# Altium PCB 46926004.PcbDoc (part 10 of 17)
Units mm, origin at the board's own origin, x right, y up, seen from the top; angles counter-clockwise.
Board outline 250 x 200 mm, 6 copper layers (Top Layer, INT1_GND, INT2_SIG, INT3_SIG, INT4_GND, Bottom Layer), stack 1.71 mm thick; 1450 components, 1293 nets, 5656 pads, 2307 vias.
Unrouted connection lines stored in the file: 2.
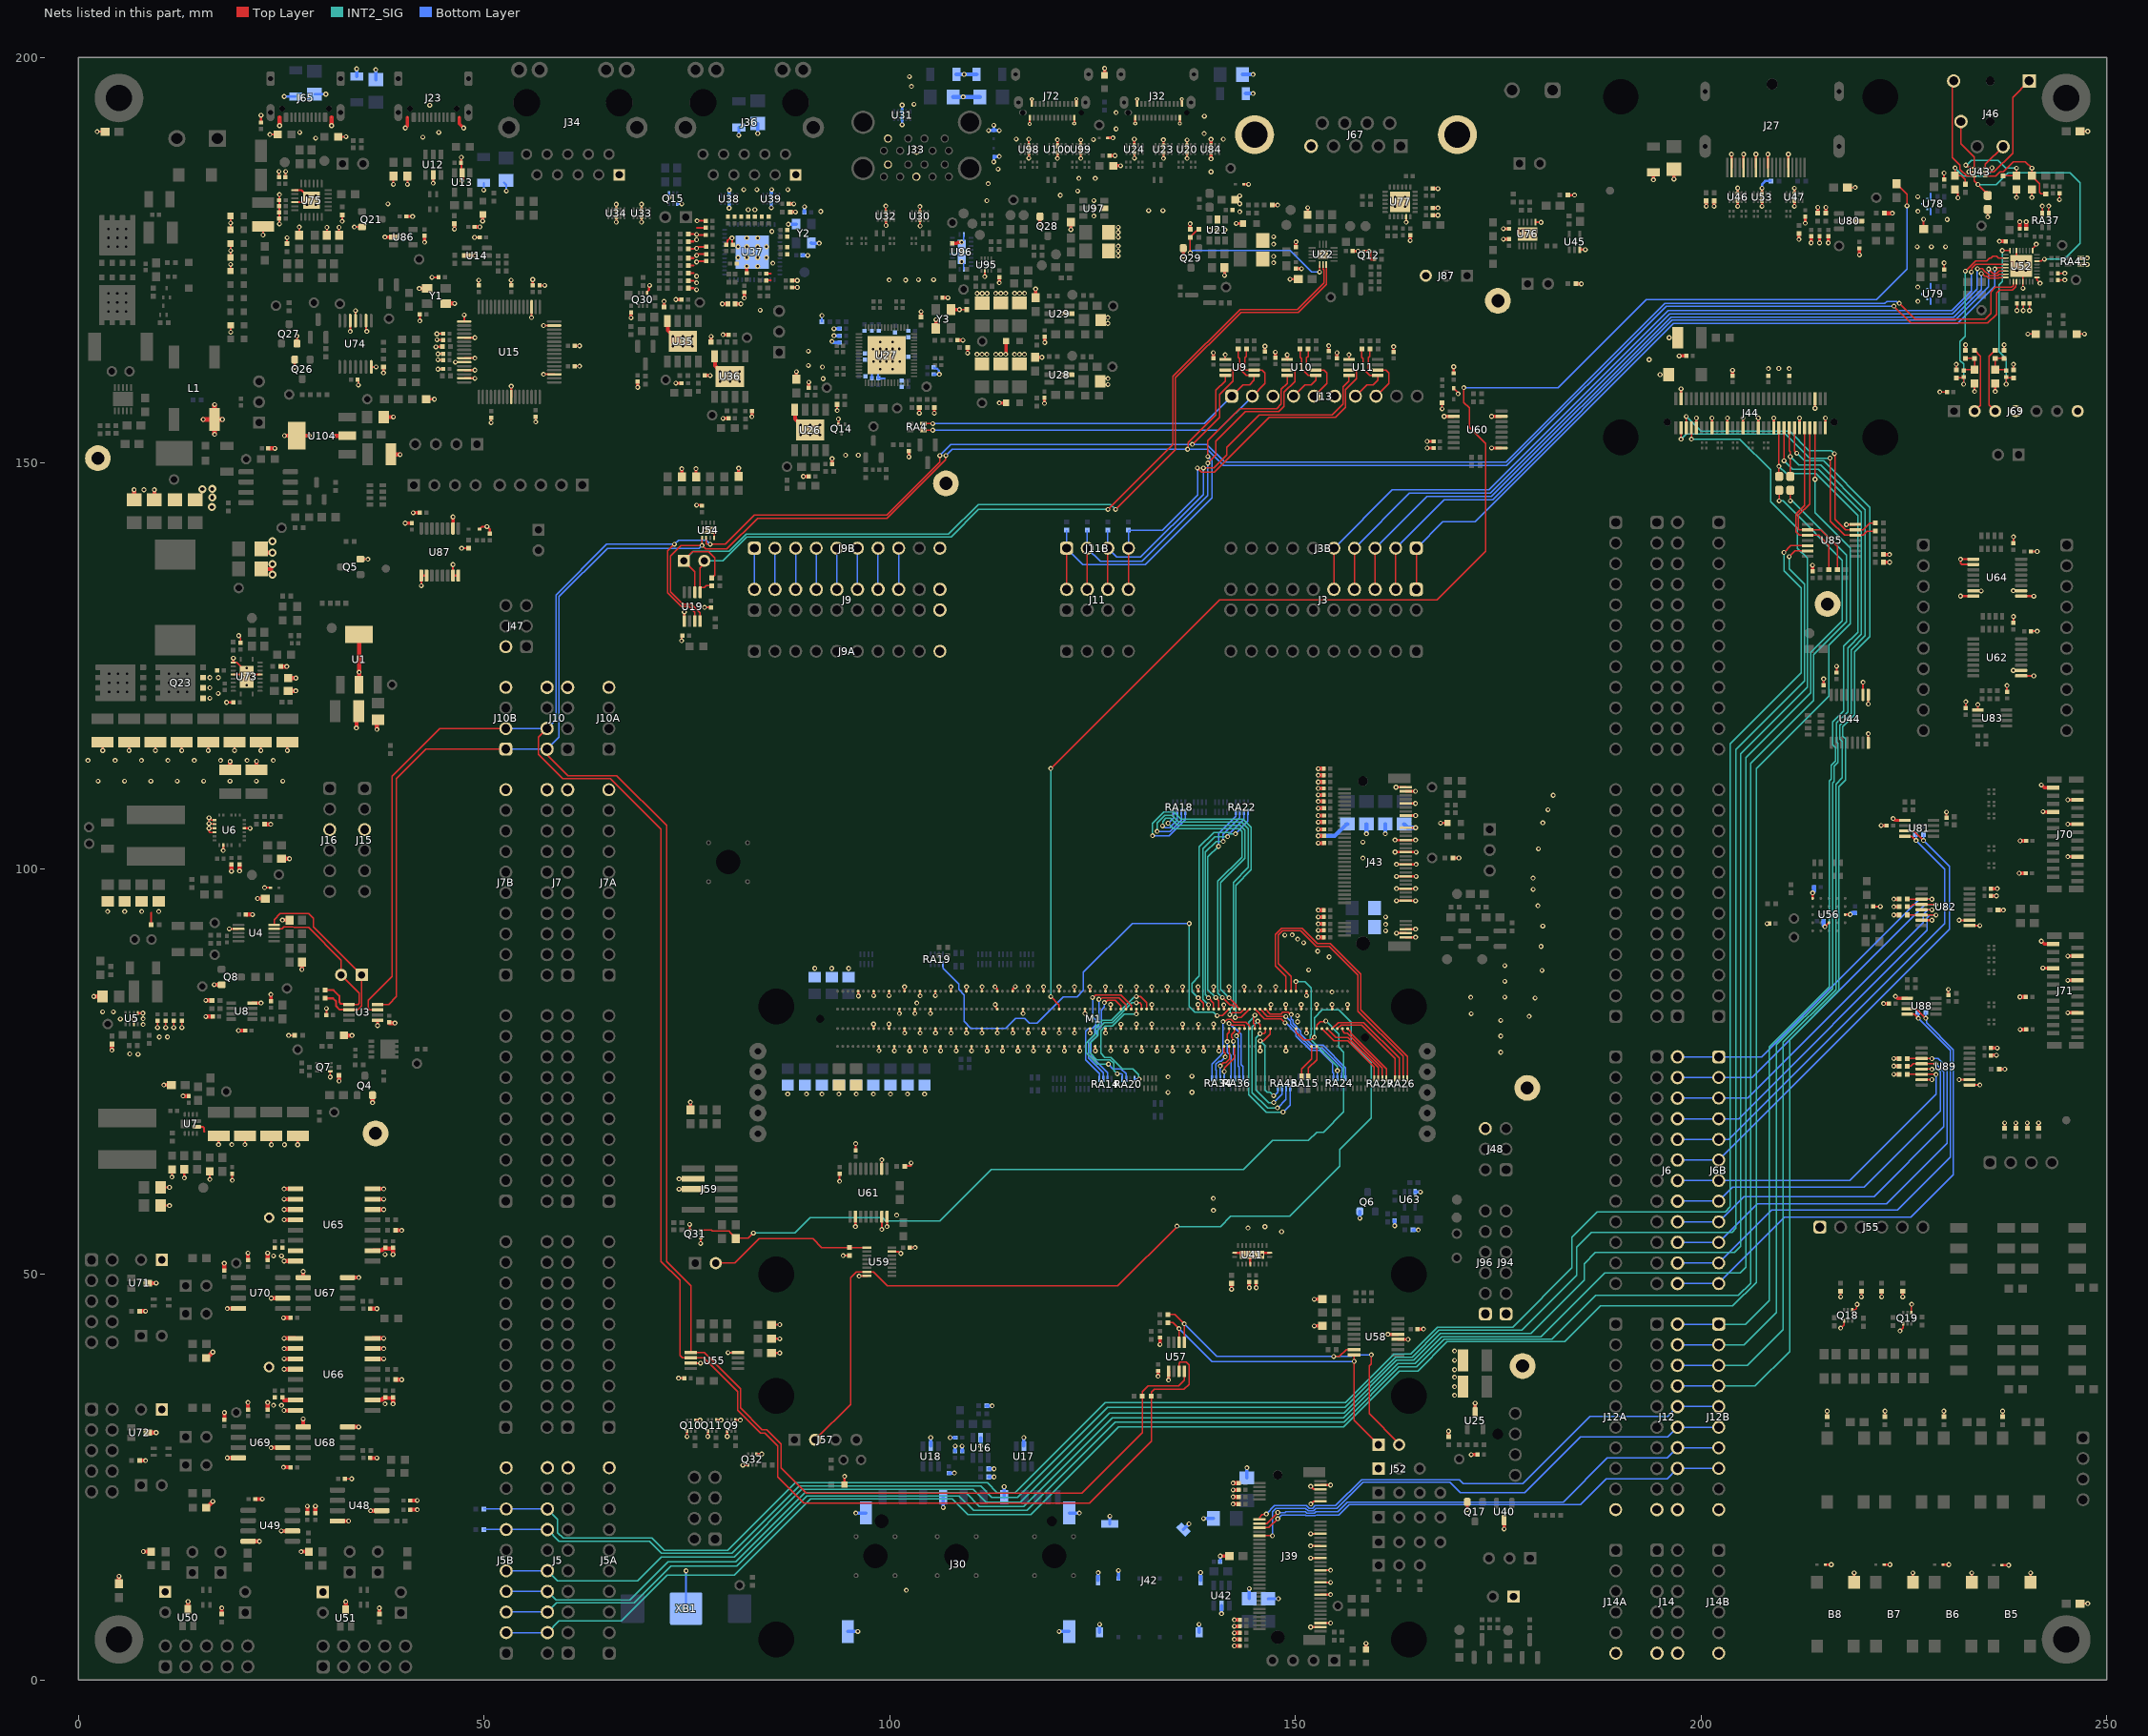
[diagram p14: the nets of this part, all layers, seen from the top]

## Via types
v1: diameter 0.6, hole 0.3, Top Layer to Bottom Layer, tented both sides, 2171 vias
v2: diameter 0.6, hole 0.3, Top Layer to Bottom Layer, 48 vias
v3: diameter 1, hole 0.5, Top Layer to Bottom Layer, tented both sides, 37 vias
v4: diameter 0.5, hole 0.2, Top Layer to Bottom Layer, tented both sides, 34 vias
v5: diameter 0.6, hole 0.3, Top Layer to Bottom Layer, tented bottom, 17 vias

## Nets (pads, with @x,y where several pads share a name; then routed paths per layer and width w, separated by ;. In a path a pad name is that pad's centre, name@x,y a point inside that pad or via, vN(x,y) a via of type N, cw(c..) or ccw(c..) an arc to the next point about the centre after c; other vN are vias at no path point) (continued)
GND: (continued)
  other v1: 102.035,11.07 79.202,32.039 81.582,32.039 37.79,34.035 169.6,35.1 169.6,36.15 169.6,37.325 169.6,38.25 169.6,39.4 169.6,40.55 37.795,52.45 148.3,55.26 144.151,55.72 146.233,55.875 100.85,57.3 139.895,57.891 139.879,59.358 18.905,66 25.405,65.983 87.425,72.235 89.725,72.235 91.639,72.235 93.739,72.235 95.865,72.235 97.989,72.235 100.089,72.235 102.189,72.235 104.289,72.235 134.3,72.425 137.25,72.45 231.804,73.998 134.3,74.342 137.25,74.425 7.35,77.125 6.325,77.175 175.3,77.375 9.972,79.254 10.972,79.254 175.3,79.375 7.972,80.801 150.262,81.134 175.3,81.3 5.175,81.475 7.975,81.5 178.8,81.8 150.26,81.882 171.658,82.122 2.975,82.35 4.3,82.35 22.5,83.45 103.334,83.439 179.528,84.057 171.608,84.147 175.8,84.175 230.473,85.118 107.537,85.444 175.8,86.125 180.4,87.463 151.629,87.526 90.75,87.715 92.85,87.715 94.925,87.715 175.8,88.05 154.152,89.126 152.741,89.839 180.281,90.424 151.024,90.883 150.271,91.329 148.7,91.815 149.609,91.843 161.115,92.35 180.49,92.931 161.12,93.135 231.805,93.65 161.115,94.049 218.375,94.36 3.6,94.731 5.7,94.731 7.8,94.731 9.9,94.731 179.891,95.427 179.301,97.45 179.291,98.835 19.862,99.714 158.312,101.3 179.95,102.452 158.312,103.275 180.49,105.66 230.235,106.97 181.125,107.262 181.771,109.05 2.433,110.8 5.683,110.8 8.933,110.8 12.183,110.8 15.433,110.8 18.683,110.8 21.933,110.8 25.183,110.8 1.175,113.35 4.525,113.35 7.775,113.35 11.025,113.35 14.275,113.35 17.525,113.35 20.775,113.35 24.025,113.35 17.243,121.602 16.192,122.295 219.961,122.989 16.192,123.565 17.245,123.565 241.014,123.764 34.6,124.232 238.486,124.436 241.014,133.589 231.986,133.611 234.514,134.239 238.486,134.261 213.728,137.407 223.231,138.728 77.12,141.713 78.12,141.713 8.08,146.71 94.549,150.97 96.12,150.97 126.886,159.682 91.791,160.399 126.886,160.407 194.95,160.9 203.878,161.445 208.3,161.654 210.85,161.654 209.575,161.66 91.695,161.835 89.976,162.034 193.6,162.75 110.749,163.409 111.372,163.409 111.975,163.409 113.073,163.409 113.696,163.409 115.373,163.409 115.996,163.409 116.599,163.409 89.976,163.791 196.065,165.45 126.88,167.213 126.88,167.938 84.035,168.835 79.367,169.627 226.725,169.925 82.061,170.348 110.776,170.918 111.399,170.918 112.002,170.918 113.064,170.928 113.687,170.928 114.289,170.928 115.388,170.928 116.012,170.928 116.614,170.928 76.195,171.367 226.7,171.7 76.195,172.217 99.925,172.572 101.96,172.56 103.533,172.6 105.412,172.597 76.195,173.037 85.589,174.641 147.31,174.686 76.195,174.788 108.86,174.825 147.315,175.471 128.15,175.532 76.195,175.603 128.15,176.135 76.195,176.469 226.625,176.65 228.375,176.65 230.125,176.65 128.15,176.758 147.31,176.986 76.195,177.522 128.15,177.836 147.31,177.886 76.195,178.19 128.15,178.438 85.475,178.55 139.42,178.739 140.37,178.736 141.32,178.739 128.15,179.062 99.542,179.288 163.649,179.688 230.325,180.025 125.161,180.448 143.151,180.976 91.5,181.025 226.725,181.041 131.9,181.113 133.663,181.113 82.55,181.225 83.375,181.225 125.158,181.398 103.712,181.629 200.62,181.648 201.595,181.648 38.15,181.95 143.136,181.963 111.971,182.343 125.161,182.348 226.7,182.816 143.12,182.95 121.011,183.021 123.175,183.529 82,183.7 83.625,183.7 87.45,183.7 112.133,184.45 123.31,185.093 125.328,185.093 139.6,185.901 113.35,186.225 136.637,187.567 136.65,189.825 125.111,189.87 141.115,189.921 115.581,189.94 29.241,190.05 42.45,190.164 138.746,190.624 27.27,190.76 44.425,190.76 127.892,191.189 138.783,192.76 127.9,193.2 43.305,194.101 102.986,194.228 102.675,196.425 102.425,197.625
  other v2: 88.991,153.481 90.191,153.481 91.391,153.481 90.191,154.681 91.391,154.681 79.095,160.067 80.295,160.067 81.495,160.067 80.295,161.267 81.495,161.267 73.29,164.404 74.49,164.404 75.69,164.404 74.49,165.604 75.69,165.604 238.921,173.725 240.021,173.725 83.728,174.25 240.021,174.825 81.3,175.321 82.371,175.321 83.728,175.321 84.8,175.321 81.3,176.678 82.371,176.678 83.728,176.678 84.8,176.678 82.371,177.75 83.728,177.75 177.813,177.838 178.6,177.838 179.387,177.838 177.813,178.625 178.6,178.625 179.387,178.625 162.3,181.6 163.5,181.6 29.275,181.85 162.3,182.8 163.5,182.8 29.275,182.95
  other v3: 23.925,136.24 23.925,137.535 23.925,140.355 16.455,144.575 16.485,145.755 15.29,146.795 16.485,146.805
  other v5: 100.368,161.58 100.378,162.495 97.983,162.52 98.808,162.51 99.604,162.5 101.228,162.515 98.823,163.29 100.368,163.3 97.968,164.065 98.803,164.07 99.594,164.05 100.363,164.07 101.168,164.07 100.373,164.92 98.818,164.935 153.396,175.715
GND_ISO1: C254.1 C255.1 C257.1 C261.1 C262.1 C263.2 C356.1 J89.1 R381.2 U65.9 U65.10 U65.11 U65.12 U65.15 U65.16 U67.5 U70.2 U70.8 U71.3 X85.1 | length 16.4
  Top Layer w0.15: C263.2@15.775,39.667 C263.2@15.825,39.667 ; v1@16.576,40.418 v1(16.576,40.429) ; U65.16@26.743,51.642 U65.16@26.748,51.647
  Top Layer w0.5: R381.2@7.55,45.467 v1(8.275,45.467) ; U71.3@8.575,48.917 v1(9.575,48.917) ; C263.2@15.825,39.667 v1@16.576,40.418 ; C261.1@17.978,50.585 v1(17.978,51.358) ; v1(18.351,45.794) U70.8@19.718,45.794 ; C255.1@20.9,51.85 v1(20.9,52.623) ; C262.1@23.323,51.85 v1(23.323,52.623) ; v1(23.765,47.065) U70.2@25.181,47.065 ; v1(25.282,44.64) C356.1@26.055,44.64 ; v1(25.353,56.725) U65.12@26.746,56.725 ; v1(25.353,57.995) U65.11@26.746,57.995 ; v1(25.353,59.265) U65.10@26.746,59.265 ; v1(25.353,60.535) U65.9@26.746,60.535 ; v1(25.355,51.647) U65.16@26.748,51.647 ; U67.5@27.705,49.606 v1(27.705,50.355)
  other v1: 24.045,52.275 25.03,52.275
GND_ISO2: C253.1 C256.1 C258.1 C259.1 C260.1 C264.2 C357.1 J85.1 R380.2 U66.9 U66.10 U66.11 U66.12 U66.15 U66.16 U68.5 U69.2 U69.8 U72.3 X84.1 | length 17.8
  Top Layer w0.15: C264.2@15.775,21.25 C264.2@15.825,21.25 ; v1@16.576,22.001 v1(16.576,22.012) ; U69.8@19.717,27.375 U69.8@19.72,27.378 ; U66.16@26.743,33.225 U66.16@26.748,33.23
  Top Layer w0.5: R380.2@7.55,27.05 v1(8.275,27.05) ; U72.3@8.575,30.5 v1(9.575,30.5) ; C264.2@15.825,21.25 v1@16.576,22.001 ; C260.1@18,32.19 v1(18,32.963) ; v1(18.35,27.375) U69.8@19.717,27.375 ; C253.1@20.9,33.435 v1(20.9,34.208) ; C259.1@23.325,33.435 v1(23.325,34.208) ; v1(23.76,28.635) 23.767,28.641 24.9,28.641 U69.2@24.908,28.65 ; v1(25.275,26.223) C357.1@26.048,26.223 ; v1(25.35,33.225) U66.16@26.743,33.225 ; 25.352,34.498 U66.15@26.745,34.498 ; v1(25.352,38.308) U66.12@26.745,38.308 ; v1(25.352,39.578) U66.11@26.745,39.578 ; v1(25.352,40.848) U66.10@26.745,40.848 ; v1(25.352,42.118) U66.9@26.745,42.118 ; U68.5@27.705,31.188 v1(27.705,32.188)
  other v1: 24.04,33.853 25.025,33.853
GPIO_01: M1.D23 RA34.4 | length 4.5
  Top Layer w0.15: v1(141.225,75.002) 141.225,75.46 142.462,76.697 M1.D23@142.462,78.1
  Bottom Layer w0.15: RA34.4@141.225,74.15 v1(141.225,75.002)
GPIO_01_JMP: J9.2 J9B.1 | length 5.1
  Bottom Layer w0.15: J9.2@83.32,134.43 J9B.1@83.32,139.51
GPIO_02: M1.D24 RA34.3 | length 4.7
  Top Layer w0.15: v1(140.736,75.689) 141.155,76.108 141.449,76.108 141.896,76.555 141.896,77.262 141.827,77.331 M1.D24@141.827,78.1
  Bottom Layer w0.15: RA34.3@140.725,74.15 140.725,74.778 140.7,74.803 140.7,75.653 v1(140.736,75.689)
GPIO_02_JMP: J9.4 J9B.2 | length 5.1
  Bottom Layer w0.15: J9.4@85.86,134.43 J9B.2@85.86,139.51
GPIO_03: M1.D25 RA34.2 | length 4.6
  Top Layer w0.15: M1.D25@141.192,78.1 141.192,77.4 141.35,77.242 v1(141.35,76.799)
  Bottom Layer w0.15: RA34.2@140.225,74.15 140.225,75.171 140.211,75.185 140.211,75.906 140.579,76.274 140.825,76.274 v1(141.35,76.799)
GPIO_03_JMP: J9.6 J9B.3 | length 5.1
  Bottom Layer w0.15: J9.6@88.4,134.43 J9B.3@88.4,139.51
GPIO_04: M1.C20 RA34.1 | length 11.6
  Top Layer w0.15: v1(141.095,81.158) 141.181,81.244 141.395,81.244 141.604,81.453 142.047,81.453 142.438,81.062 143.905,81.062 144.367,80.601 M1.C20@144.367,80.3
  Bottom Layer w0.15: RA34.1@139.725,74.15 139.725,75.924 140.6,76.799 141.095,77.294 141.095,78.407 141.079,78.423 141.079,79.537 141.095,79.553 v1(141.095,81.158)
GPIO_04_JMP: J9.8 J9B.4 | length 5.1
  Bottom Layer w0.15: J9.8@90.94,134.43 J9B.4@90.94,139.51
GPIO_05: M1.C21 RA36.4 | length 10
  Top Layer w0.15: v1(141.821,80.928) 141.939,80.928 142.134,80.733 143.644,80.733 143.732,80.645 M1.C21@143.732,80.3
  Bottom Layer w0.15: v1(141.821,80.928) 142.337,80.412 142.484,80.412 143.3,79.596 143.3,75.879 143.55,75.629 RA36.4@143.55,74.15
GPIO_05_JMP: J9.10 J9B.5 | length 5.1
  Bottom Layer w0.15: J9.10@93.48,134.43 J9B.5@93.48,139.51
GPIO_06: M1.C22 RA36.3 | length 6.4
  Top Layer w0.15: v1(142.726,79.399) 142.726,79.506 143.097,79.876 M1.C22@143.097,80.3
  Bottom Layer w0.15: v1(142.726,79.399) 142.726,79.277 142.957,79.046 142.957,75.648 143.05,75.554 RA36.3@143.05,74.15
GPIO_06_JMP: J9.12 J9B.6 | length 5.1
  Bottom Layer w0.15: J9.12@96.02,134.43 J9B.6@96.02,139.51
GPIO_07: M1.C23 RA36.2 | length 6.4
  Top Layer w0.15: v1(142.353,78.718) 142.267,78.805 142.267,79.145 142.145,79.266 142.145,79.566 142.462,79.883 M1.C23@142.462,80.3
  Bottom Layer w0.15: v1(142.353,78.718) 142.353,77.141 142.55,76.944 RA36.2@142.55,74.15
GPIO_07_JMP: J9.14 J9B.7 | length 5.1
  Bottom Layer w0.15: J9.14@98.56,134.43 J9B.7@98.56,139.51
GPIO_08: M1.C24 RA36.1 | length 6.4
  Top Layer w0.15: v1(141.604,78.687) 141.604,79.6 141.826,79.822 M1.C24@141.827,80.3 M1.C24@141.827,80.3
  Bottom Layer w0.15: v1(141.604,78.687) 141.604,77.404 142.05,76.958 RA36.1@142.05,74.15
GPIO_08_JMP: J9.16 J9B.8 | length 5.1
  Bottom Layer w0.15: J9.16@101.1,134.43 J9B.8@101.1,139.51
GPIO_09_CSI_1: M1.B17 RA24.4 | length 15.1
  Top Layer w0.15: M1.B17@146.272,82.7 146.864,82.108 148.212,82.108 148.389,82.285 149.127,82.285 149.374,82.039 v1(149.496,82.039)
  Bottom Layer w0.15: v1(149.496,82.039) 149.496,81.508 149.689,81.315 149.689,80.965 150.671,79.983 150.671,79.64 152.069,78.242 153.401,78.242 156.175,75.469 RA24.4@156.175,74.178
GPIO_09_CSI_1_JMP: J6.2 J6B.1 R360.2 U82.3 | length 42.4
  Top Layer w0.15: R360.2@225.43,96.25 U82.3@227.18,96.25 v1@228.432,96.25
  Bottom Layer w0.15: J6.2@197.09,76.8 200.84,76.8 J6B.1@202.17,76.8 207.482,76.8 226.921,96.239 v1(228.443,96.239)
GPIO_10_CSI_1: M1.B18 RA24.3 | length 14.8
  Top Layer w0.15: M1.B18@145.637,82.7 146.529,81.808 148.752,81.808 v1(148.8,81.76)
  Bottom Layer w0.15: v1(148.8,81.76) 149.389,81.171 149.389,80.841 149.623,80.607 150.371,79.859 150.371,79.516 151.985,77.902 153.317,77.902 155.771,75.449 155.771,74.948 155.675,74.852 RA24.3@155.675,74.178
GPIO_10_CSI_1_JMP: J6.4 J6B.2 R361.2 U82.4 | length 44.3
  Top Layer w0.15: R361.2@225.43,95.319 225.453,95.343 225.867,95.343 226.124,95.6 U82.4@227.18,95.6 ; U82.4@227.187,95.592 v1@228.947,95.592
  Bottom Layer w0.15: J6.4@197.09,74.26 200.84,74.26 J6B.2@202.17,74.26 206.26,74.26 227.585,95.585 v1(228.955,95.585)
GPIO_11_CSI_1: M1.A11 RA24.2 | length 16
  Top Layer w0.18: v1(150.059,86.09) 150.083,86.066 M1.A11@150.083,84.9
  INT2_SIG w0.15: v1(150.059,86.09) 151.178,86.09 151.928,85.34 151.928,79.571 151.8,79.443 151.8,79.101 151.801,79.1 151.801,79.007 155.175,75.633 v1(155.175,75.095)
  Bottom Layer w0.15: RA24.2@155.175,74.178 v1(155.175,75.095)
GPIO_11_CSI_1_JMP: J6.6 J6B.3 U82.5 | length 42.8
  Top Layer w0.15: U82.5@227.18,94.95 v1@228.432,94.95
  Bottom Layer w0.15: J6.6@197.09,71.72 200.84,71.72 J6B.3@202.17,71.72 205.777,71.72 227.4,93.343 227.4,94.364 227.975,94.939 v1(228.443,94.939)
GPIO_12_CSI_1: M1.B19 RA24.1 | length 14.4
  Top Layer w0.15: M1.B19@145.002,82.7 146.194,81.508 148.217,81.508 v1(148.725,81)
  Bottom Layer w0.15: v1(148.725,81) 148.806,81 150.059,79.746 150.059,79.403 151.875,77.588 153.025,77.588 154.578,76.035 154.578,74.884 154.675,74.788 RA24.1@154.675,74.178
GPIO_12_CSI_1_JMP: J6.8 J6B.4 R362.2 U82.6 | length 46.7
  Top Layer w0.15: R362.2@225.43,94.3 U82.6@227.18,94.3 v1@228.94,94.3
  Bottom Layer w0.15: J6.8@197.09,69.18 200.84,69.18 J6B.4@202.17,69.18 204.62,69.18 227.869,92.429 227.869,93.941 228.221,94.292 v1(228.947,94.292)
GPIO_13_CSI_2: M1.C01 RA27.1 | length 8.1
  Top Layer w0.15: M1.C01@156.432,80.3 156.825,79.907 156.825,79.725 161.203,75.347 RA27.1@161.203,74.128
GPIO_13_CSI_2_JMP: J6.20 J6B.10 R368.2 U89.3 | length 52.9
  Top Layer w0.15: R368.2@225.429,76.598 U89.3@227.179,76.598 v1@228.432,76.598
  Bottom Layer w0.15: J6.20@197.09,53.94 J6B.10@202.17,53.94 206.93,58.7 222.839,58.7 230.3,66.161 230.3,75.499 229.212,76.587 v1(228.443,76.587)
GPIO_14_CSI_2: M1.C02 RA27.2 | length 8.4
  Top Layer w0.15: M1.C02@155.797,80.3 155.797,80.003 156.05,79.75 156.376,79.75 160.703,75.423 RA27.2@160.703,74.128
GPIO_14_CSI_2_JMP: J6.18 J6B.9 R369.2 U89.4 | length 49.4
  Top Layer w0.15: R369.2@225.429,75.668 225.453,75.691 225.867,75.691 226.124,75.948 U89.4@227.179,75.948 ; U89.4@227.187,75.941 v1@228.947,75.941
  Bottom Layer w0.15: J6.18@197.09,56.48 J6B.9@202.17,56.48 205.293,59.603 221.308,59.603 229.9,68.195 229.9,74.988 v1(228.954,75.933)
GPIO_15_CSI_2: M1.C03 RA26.4 | length 11.5
  Top Layer w0.15: M1.C03@155.162,80.3 155.612,80.75 158.174,80.75 162.285,76.638 RA26.4@162.285,74.128
GPIO_15_CSI_2_JMP: J6.16 J6B.8 U89.5 | length 44.3
  Top Layer w0.15: U89.5@227.179,75.298 v1@228.432,75.298
  Bottom Layer w0.15: J6.16@197.09,59.02 200.84,59.02 J6B.8@202.17,59.02 203.885,60.735 220.074,60.735 229.5,70.161 229.5,74.963 229.176,75.287 v1(228.443,75.287)
GPIO_16_CSI_2: M1.C04 RA26.3 | length 12.9
  Top Layer w0.15: M1.C04@154.527,80.3 155.277,81.05 158.425,81.05 162.785,76.69 RA26.3@162.785,74.128
GPIO_16_CSI_2_JMP: J6.14 J6B.7 R370.2 U89.6 | length 42.2
  Top Layer w0.15: R370.2@225.429,74.648 U89.6@227.179,74.648 v1@228.939,74.648
  Bottom Layer w0.15: J6.14@197.09,61.56 200.84,61.56 J6B.7@202.17,61.56 218.316,61.56 228.979,72.223 228.979,74.608 v1(228.947,74.641)
GPIO_17_DSI_1: M1.B42 RA20.4 | length 15.6
  Top Layer w0.15: v1@130.397,82.093 M1.B42@130.397,82.7
  INT2_SIG w0.15: v1(130.394,82.09) 128.914,82.09 127.424,80.6 126.563,80.6 126,80.037 126,77.265 126.508,76.757 127.266,76.757 128.689,75.333 129.953,75.333 130.684,74.603 130.684,74.143 v1(130.75,74.078)
  Bottom Layer w0.15: RA20.4@130.15,74.072 130.156,74.078 v1(130.75,74.078)
GPIO_17_DSI_1_JMP: J5.10 J5B.5 J44.8 | length 286
  Top Layer w0.15: J44.8@198.797,154.35 198.799,154.349 198.799,152.956 v1(198.8,152.955)
  INT2_SIG w0.15: J5.10@57.81,13.46 59.07,12.2 68.9,12.2 71.875,15.175 80.832,15.175 89.157,23.5 110.262,23.5 111.862,21.9 116.1,21.9 127.1,32.9 155.976,32.9 162.476,39.4 164.547,39.4 167.847,42.7 179.014,42.7 185.6,49.286 185.6,51.3 186.985,52.685 204.116,52.685 204.9,53.469 204.9,114.162 213.1,122.362 213.1,138.296 211.89,139.506 211.89,141.95 208.576,145.264 208.576,149.162 204.783,152.955 v1(198.8,152.955)
  Bottom Layer w0.15: J5B.5@52.73,13.46 J5.10@57.81,13.46
GPIO_18_DSI_1: M1.B43 RA14.1 | length 17.6
  Top Layer w0.15: v1(124.996,84.113) 125.077,84.113 125.39,84.427 128.483,84.427 129.762,83.148 M1.B43@129.762,82.7
  Bottom Layer w0.15: v1(124.996,84.113) 125.021,84.088 125.021,81.756 125.386,81.392 125.386,80.72 124.989,80.323 124.476,80.323 124.121,79.969 124.121,76.452 125.825,74.749 RA14.1@125.825,74.072
GPIO_18_DSI_1_JMP: J5.8 J5B.4 JP3.2 | length 275.8
  Top Layer w0.15: v1(209.625,145.35) JP3.2@209.625,146.65
  INT2_SIG w0.15: J5.8@57.81,10.92 58.86,9.87 67.97,9.87 72.7,14.6 81.018,14.6 89.518,23.1 109.375,23.1 111.075,21.4 116.538,21.4 127.438,32.3 155.911,32.3 162.611,39 164.734,39 168.039,42.305 180.24,42.305 188.136,50.2 204.806,50.2 205.5,50.894 205.5,113.675 213.489,121.664 213.489,126.661 217.395,130.568 217.395,138.031 210.677,144.748 210.076,145.35 v1(209.625,145.35)
  Bottom Layer w0.15: J5B.4@52.73,10.92 J5.8@57.81,10.92
GPIO_19_DSI_1: M1.B44 RA14.2 | length 15.4
  Top Layer w0.15: v1(125.774,83.902) 125.86,83.988 126.064,83.988 126.151,84.075 128.271,84.075 129.127,83.219 M1.B44@129.127,82.7
  Bottom Layer w0.15: v1(125.774,83.902) 125.774,80.684 125.268,80.178 125.268,79.581 124.496,78.809 124.496,76.662 126.325,74.834 RA14.2@126.325,74.072
GPIO_19_DSI_1_JMP: J5.6 J5B.3 JP4.2 | length 277.3
  Top Layer w0.15: v1(211,145.35) JP4.2@211,146.65
  INT2_SIG w0.15: J5.6@57.81,8.38 58.93,9.5 68.48,9.5 73.052,14.072 81.147,14.072 89.775,22.7 108.535,22.7 110.335,20.9 116.9,20.9 127.8,31.8 155.976,31.8 162.776,38.6 164.9,38.6 168.305,42.005 181.605,42.005 187,47.4 204.6,47.4 206.1,48.9 206.1,113 213.845,120.745 213.845,126.362 217.904,130.421 217.904,138.648 211.202,145.35 v1(211,145.35)
  Bottom Layer w0.15: J5B.3@52.73,8.38 J5.6@57.81,8.38
GPIO_20_DSI_1: M1.B45 RA14.3 | length 13.8
  Top Layer w0.15: v1(126.45,83.511) 126.572,83.511 126.836,83.775 127.814,83.775 128.492,83.097 M1.B45@128.492,82.7
  Bottom Layer w0.15: v1(126.45,83.511) 126.45,82.946 126.075,82.571 126.075,80.553 125.568,80.046 125.568,79.457 125.54,79.429 125.54,79.398 124.805,78.663 124.805,76.885 126.825,74.864 RA14.3@126.825,74.072
GPIO_20_DSI_1_JMP: J5.4 J5B.2 J44.56 | length 285.5
  Top Layer w0.15: v1(214.037,148) J44.56@214.037,154.35
  INT2_SIG w0.15: J5.4@57.81,5.84 59.25,7.28 66.905,7.28 72.56,12.935 80.86,12.935 90.225,22.3 107.724,22.3 109.624,20.4 117.4,20.4 128.2,31.2 155.934,31.2 162.834,38.1 165.1,38.1 168.705,41.705 183.212,41.705 187.607,46.1 203.9,46.1 206.8,49 206.8,112.31 215.753,121.263 215.753,127.543 218.4,130.19 218.4,139.514 214.037,143.876 v1(214.037,148)
  Bottom Layer w0.15: J5B.2@52.73,5.84 J5.4@57.81,5.84
GPIO_21_DP: M1.B57 R217.2 | length 187.8
  Top Layer w0.15: v1(119.842,84.24) 120.857,83.225 120.857,82.715 M1.B57@120.866,82.706 ; v1(119.842,112.348) 140.654,133.16 167.471,133.16 173.45,139.139 173.45,152.387 171.426,154.411 171.426,156.814 170.75,157.49 v1(170.75,159.3) ; R217.2@224.075,184.425 225.375,183.125 v1(225.375,181.717)
  INT2_SIG w0.15: v1(119.842,84.24) v1(119.842,112.348)
  Bottom Layer w0.15: v1(170.75,159.3) 182.375,159.3 193.237,170.162 221.612,170.162 225.375,173.925 v1(225.375,181.717)
HP_FB: J46.4 JP2.2 U43.3 U52.14 | length 43.9
  Top Layer w0.15: J46.4@231.125,197.1 230.975,197.1 230.975,187.675 231.925,186.725 231.925,186.208 232.758,185.375 U43.3@233.66,185.375 ; U43.3@233.478,185.444 233.591,185.444 U43.3@233.66,185.375 ; JP2.2@235.325,183.493 234.957,183.493 233.66,184.79 U43.3@233.66,185.375 ; U52.14@241.396,174.875 241.406,174.885 241.942,174.885 242.188,175.131 v1(242.31,175.131)
  INT2_SIG w0.15: v1(234.112,184.338) 236.375,184.338 237.812,185.775 245.475,185.775 246.725,184.525 246.725,177.1 244.756,175.131 v1(242.31,175.131)
HP_LEFT: C184.2 J46.2 L10.2 U43.1 | length 17.1
  Top Layer w0.15: J46.2@232.025,192.1 232.025,189.35 233.66,187.715 U43.1@233.66,186.375 233.267,186.375 233.167,186.475 232.875,186.475 v1(232.625,186.725) ; L10.2@237.225,185.4 C184.2@238.875,185.4 v1(238.875,186.35)
  INT2_SIG w0.15: v1(232.625,186.725) 232.724,186.725 233.295,187.296 236.604,187.296 237.55,186.35 v1(238.875,186.35)
HP_MICIN: C336.2 J46.1 L12.2 U43.4 U43.5 | length 25.6
  Top Layer w0.15: J46.1@240.425,197.1 238.4,195.075 238.4,188.175 236.1,185.875 U43.5@235.04,185.875 U43.4@235.04,185.375 236.282,185.375 236.832,185.925 237.275,185.925 238.5,187.15 239.975,187.15 v1(240.775,186.35) C336.2@240.775,185.4 240.775,185.35 241.725,184.4 241.725,183.35 241.875,183.2 242.45,183.2 L12.2@242.475,183.175
HP_RIGHT: C189.2 J46.3 L11.2 U43.6 | length 13.1
  Top Layer w0.15: C189.2@231.3,185.4 232.1,185.4 232.525,184.975 232.525,184.425 L11.2@232.575,184.375 ; v1(231.3,186.375) 231.3,185.675 C189.2@231.575,185.4 ; v1(235.85,186.4) 235.85,186.375 U43.6@235.04,186.375 235.04,186.815 J46.3@237.225,189
  INT2_SIG w0.15: v1(231.3,186.375) 232.325,185.35 235.2,185.35 235.85,186 235.85,186.375 v1(235.85,186.4)
I2C1_SCL_3V: J13.2 R73.2 RA4.1 U9.6 | length 51
  Top Layer w0.15: RA4.1@104.132,154.059 v1(105.314,154.059) ; R73.2@143.955,164.059 143.945,164.049 143.945,163.185 143.745,162.985 143.745,161.625 143.895,161.475 U9.6@144.9,161.475 145.895,161.475 145.97,161.4 146.252,161.118 146.252,159.812 J13.2@144.69,158.25
  Bottom Layer w0.15: v1(105.314,154.059) 140.499,154.059 J13.2@144.69,158.25
I2C1_SCL_FAN_5V: J51.1 R250.2 U57.6 U58.16 | length 38.9
  Top Layer w0.15: R250.2@134.302,44.05 134.917,44.05 v1(135.652,43.315) U57.6@135.652,41.605 ; U58.16@157.237,40.077 v1(157.237,39.275) 157.237,32 J51.1@160.237,29
  Bottom Layer w0.15: v1(135.652,43.315) 139.692,39.275 v1(157.237,39.275)
I2C1_SCL_PWRMES_3V: J22.1 R14.2 U3.6 U4.5 | length 24.9
  Top Layer w0.15: U4.5@24.125,93.075 24.125,93.732 24.869,94.476 28.391,94.476 28.975,93.892 28.975,92.855 J22.1@34.917,86.913 34.917,83.094 34.448,82.625 U3.6@33.33,82.625
  Top Layer w0.25: R14.2@30.425,84.025 31.375,84.025 31.75,83.65 31.75,83.075 32.2,82.625 U3.6@33.33,82.625
I2C1_SDA_3V: J13.1 R71.2 RA4.2 U9.5 | length 48.2
  Top Layer w0.15: RA4.2@104.132,154.859 v1(105.313,154.859) ; J13.1@142.15,158.25 143.55,159.65 144.345,159.65 144.9,160.205 U9.5@144.9,160.825 143.945,160.825 143.13,161.64 143.13,162.873 142.95,163.053 R71.2@142.95,164.059
  Bottom Layer w0.15: v1(105.313,154.859) 138.759,154.859 J13.1@142.15,158.25
I2C1_SDA_FAN_5V: J51.2 R249.2 U57.5 U58.15 | length 45.1
  Top Layer w0.15: R249.2@134.302,45.05 135.152,45.05 v1(136.302,43.9) U57.5@136.302,41.605 ; v1(154.724,39.872) 155.432,39.872 156.272,40.712 U58.15@157.237,40.712 ; v1(159.359,40.077) 159.359,38.977 159.106,38.725 159.106,32.818 162.777,29.147 J51.2@162.777,29
  Bottom Layer w0.15: v1(136.302,43.9) 140.329,39.872 v1(154.724,39.872) 156.895,39.872 157.101,40.077 v1(159.359,40.077)
I2C1_SDA_PWRMES_3V: J22.2 R13.2 U3.5 U4.4 | length 21.7
  Top Layer w0.15: U4.4@24.125,92.575 25.075,92.575 25.325,92.825 26.465,92.825 26.54,92.75 28.372,92.75 32.377,88.745 J22.2@32.377,86.913 34.617,84.673 34.617,83.417 34.475,83.275 U3.5@33.33,83.275
  Top Layer w0.25: R13.2@30.425,85.025 31.45,85.025 32.15,84.325 32.15,83.55 32.35,83.35 33.255,83.35 U3.5@33.33,83.275
I2C2_SCL_3V: J13.5 R74.2 U10.6 | length 8.8
  Top Layer w0.15: R74.2@151.575,164.059 151.565,164.049 151.565,163.185 151.365,162.985 151.365,161.625 151.515,161.475 U10.6@152.52,161.475 153.515,161.475 153.59,161.4 153.872,161.118 153.872,159.812 J13.5@152.31,158.25
I2C2_SDA_3V: J13.4 R72.2 U10.5 | length 8.8
  Top Layer w0.15: J13.4@149.77,158.25 151.17,159.65 151.965,159.65 152.52,160.205 U10.5@152.52,160.825 151.565,160.825 150.75,161.64 150.75,162.873 150.57,163.053 R72.2@150.57,164.059
I2C6_SCL_3V: J13.8 R79.2 U11.6 | length 8.8
  Top Layer w0.15: R79.2@159.195,164.059 159.185,164.049 159.185,163.185 158.985,162.985 158.985,161.625 159.135,161.475 U11.6@160.14,161.475 161.135,161.475 161.21,161.4 161.492,161.118 161.492,159.812 J13.8@159.93,158.25
I2C6_SDA_3V: J13.7 R78.2 U11.5 | length 8.8
  Top Layer w0.15: J13.7@157.39,158.25 158.79,159.65 159.585,159.65 160.14,160.205 U11.5@160.14,160.825 159.185,160.825 158.37,161.64 158.37,162.873 158.19,163.053 R78.2@158.19,164.059
I2C_1_SCL: M1.D08 RA15.2 | length 4.3
  Top Layer w0.15: RA15.2@150.774,74.35 150.774,75.34 151.987,76.553 M1.D08@151.987,78.1
I2C_1_SCL_JMP: J10.4 J10B.2 R478.2 U3.3 U9.3 U19.3 U52.2 U54.2 U55.6 U57.3 | length 473.2
  Top Layer w0.15: U3.3@36.87,82.625 35.913,82.625 35.708,82.83 35.708,83.773 38.663,86.728 38.663,111.401 44.542,117.28 J10B.2@52.68,117.28 ; J10.4@57.76,117.28 56.7,116.22 56.7,114.1 59.684,111.116 65.584,111.116 71.8,104.9 71.8,51.6 74.121,49.279 74.121,40.015 74.437,39.7 U55.6@75.475,39.7 77.107,39.7 81.275,35.532 81.275,33.262 84.082,30.456 84.614,30.456 86.2,28.87 86.2,25.029 89.429,21.8 124.618,21.8 132.236,29.417 R478.2@132.236,34.978 132.236,35.493 132.59,35.848 136.273,35.848 136.876,36.451 136.876,38.853 136.565,39.164 135.806,39.164 135.652,39.01 U57.3@135.652,38.065 ; v1(73.454,140) 72.62,139.166 72.62,134.035 74.35,132.305 75.25,132.305 75.975,131.58 U19.3@75.975,130.535 ; U54.2@77.37,140.763 77.37,140.088 77.458,140 v1(77.87,140) 79.727,140 83.32,143.593 99.644,143.593 106.164,150.114 v1(106.164,150.92) ; v1(137.3,152.3) 140.665,155.665 140.665,158.448 142.295,160.079 142.295,161.387 142.207,161.475 U9.3@141.36,161.475 ; v1(224.427,169.689) 226.392,167.725 235.001,167.725 235.73,168.454 235.73,171.104 236.277,171.651 238.252,171.651 238.462,171.861 238.462,172.34 U52.2@238.471,172.35
  Bottom Layer w0.15: J10B.2@52.68,117.28 J10.4@57.76,117.28 58.865,118.385 58.865,133.75 65.115,140 v1(73.454,140) 73.954,140.5 77.37,140.5 v1(77.87,140) ; v1(106.164,150.92) 106.164,150.966 107.498,152.3 v1(137.3,152.3) 139.094,152.3 141.294,150.1 175.975,150.1 195.55,169.675 222.642,169.675 222.902,169.935 224.114,169.935 224.36,169.689 v1(224.427,169.689)
I2C_1_SCL_USBC_3V: J31.1 R103.2 U19.6 U22.8 | length 113.1
  Top Layer w0.15: U19.6@75.975,134.075 75.975,136.58 J31.1@74.605,137.95 75.705,139.05 77.7,139.05 78.45,138.3 78.45,136.21 R103.2@78.075,135.835 ; v1(127.83,144.282) 135.2,151.652 135.2,160.496 143.296,168.591 150.373,168.591 153.812,172.031 153.812,174.449 U22.8@153.796,174.465
  INT2_SIG w0.15: J31.1@74.605,137.95 75.78,139.125 80.179,139.125 82.295,141.24 107.235,141.24 110.906,144.91 127.202,144.91 v1(127.83,144.282)
I2C_1_SDA: M1.D07 RA15.1 | length 4.2
  Top Layer w0.15: RA15.1@151.574,74.35 151.574,75.417 152.622,76.465 M1.D07@152.622,78.1
I2C_1_SDA_JMP: J10.2 J10B.1 R477.2 U3.4 U9.4 U19.4 U52.3 U54.1 U55.5 U57.4 | length 463.4
  Top Layer w0.15: U3.4@36.87,83.275 38.225,83.275 39.211,84.261 39.211,111.096 42.855,114.74 J10B.1@52.68,114.74 ; J10.2@57.76,114.74 57.76,114.04 60.316,111.484 66.35,111.484 72.5,105.334 72.5,51.58 75.475,48.605 U55.5@75.475,40.35 77.151,40.35 81.582,35.919 81.582,33.543 84.275,30.85 84.85,30.85 86.6,29.1 86.6,26.122 89.694,23.028 123.674,23.028 131.118,30.472 R477.2@131.118,34.978 131.118,35.52 131.873,36.275 135.627,36.275 136.302,36.95 U57.4@136.302,38.065 ; U19.4@76.625,130.535 76.625,131.558 75.579,132.605 74.53,132.605 72.986,134.149 72.986,138.541 74.295,139.85 v1(76.87,139.85) ; U54.1@76.87,140.763 v1(76.87,139.85) ; v1(106.914,150.92) 106.861,150.866 106.861,150.386 99.666,143.191 83.717,143.191 79.927,139.4 77.32,139.4 v1(76.87,139.85) ; v1(136.705,151.7) 136.775,151.77 136.775,152.517 140.215,155.958 140.215,158.977 141.36,160.122 U9.4@141.36,160.825 ; v1(223.764,169.339) 225.853,167.25 235.325,167.25 236.425,168.35 236.425,170.975 236.801,171.351 238.376,171.351 238.762,171.737 238.762,171.874 238.862,171.974 238.862,172.34 U52.3@238.871,172.35
  Bottom Layer w0.15: J10B.1@52.68,114.74 J10.2@57.76,114.74 59.25,116.23 59.25,133.522 65.194,139.466 76.486,139.466 v1(76.87,139.85) ; v1(106.914,150.92) 107.694,151.7 139.15,151.7 141.15,149.7 176.05,149.7 195.689,169.339 v1(223.764,169.339)
I2C_1_SDA_USBC_3V: J31.2 R102.2 U19.5 U22.7 | length 102.8
  Top Layer w0.15: J31.2@77.145,137.95 77.145,137.611 76.625,137.091 76.625,134.665 76.63,134.66 77.164,134.66 77.389,134.885 R102.2@78.075,134.885 ; v1(126.896,144.282) 134.9,152.287 134.9,160.667 143.158,168.925 150.234,168.925 153.512,172.203 153.512,173.786 153.396,173.902 U22.7@153.396,174.465
  INT2_SIG w0.15: J31.2@77.145,137.95 79.445,137.95 82.395,140.9 107.551,140.9 110.951,144.3 126.878,144.3 v1(126.896,144.282)
I2C_2_SCL: M1.C17 RA45.3 | length 13.4
  Top Layer w0.15: v1(145.631,79.672) 146.098,79.672 146.272,79.846 M1.C17@146.272,80.3
  INT2_SIG w0.15: v1(145.631,79.672) 145.1,79.141 145.1,72.76 146.728,71.132 147.278,71.132 v1(147.328,71.182)
  Bottom Layer w0.15: v1(147.328,71.182) 147.712,71.566 148.35,72.204 RA45.3@148.35,72.95
I2C_2_SCL_JMP: J11.4 J11B.2 R414.2 U10.3 | length 49.4
  Top Layer w0.15: J11.4@124.34,134.43 J11B.2@124.34,139.51 ; v1(139.212,150) 140.215,151.002 140.215,152.725 143.819,156.329 147.92,156.329 148.6,157.009 148.6,158.728 149.915,160.043 149.915,161.384 149.827,161.472 U10.3@148.983,161.472
  Bottom Layer w0.15: R414.2@124.34,141.725 J11B.2@124.34,139.51 125.95,137.9 131.098,137.9 139.212,146.015 v1(139.212,150)
I2C_2_SDA: M1.C16 RA45.4 | length 11.2
  Top Layer w0.15: v1(145.65,78.78) 145.662,78.792 146.08,78.792 146.907,79.619 M1.C16@146.907,80.3
  INT2_SIG w0.15: v1(145.65,78.78) 146.226,78.203 146.226,72.742 146.548,72.421 146.905,72.421 v1(147.313,72.013)
  Bottom Layer w0.15: v1(147.313,72.013) 147.435,72.013 147.85,72.428 RA45.4@147.85,72.95
I2C_2_SDA_JMP: J11.2 J11B.1 R413.2 U10.4 | length 51.5
  Top Layer w0.15: J11.2@121.8,134.43 J11B.1@121.8,139.51 ; v1(139.212,150.8) 139.212,152.782 143.134,156.704 147.703,156.704 148.255,157.256 148.255,159.08 148.98,159.805 U10.4@148.98,160.825
  Bottom Layer w0.15: R413.2@121.8,141.725 J11B.1@121.8,139.51 123.81,137.5 131.5,137.5 139.737,145.737 139.737,150.275 v1(139.212,150.8)
I2C_3_DSI1_SCL: M1.B41 RA20.1 | length 16.9
  Top Layer w0.15: v1(130.398,83.472) 130.402,83.467 130.835,83.467 131.032,83.269 M1.B41@131.032,82.7
  INT2_SIG w0.15: v1(128.035,74.725) 127.599,75.161 127.599,76 127.141,76.457 125.507,76.457 124.67,77.294 124.67,78.473 125.7,79.503 125.7,80.264 126.46,81.024 127.424,81.024 129.872,83.472 v1(130.398,83.472)
  Bottom Layer w0.15: v1(128.035,74.725) 128.07,74.76 128.562,74.76 128.65,74.672 RA20.1@128.65,74.072
I2C_3_DSI1_SDA: M1.B40 RA20.2 | length 19.2
  Top Layer w0.15: v1(130.398,84.24) 130.89,84.24 131.667,83.463 M1.B40@131.667,82.7
  INT2_SIG w0.15: v1(126.95,75.906) 125.634,75.906 124.2,77.34 124.2,78.513 125.386,79.699 125.386,80.498 126.212,81.324 127.3,81.324 130.085,84.109 130.146,84.109 130.276,84.24 v1(130.398,84.24)
  Bottom Layer w0.15: v1(126.95,75.906) 127.523,75.333 128.502,75.333 129.125,74.71 129.125,74.097 RA20.2@129.15,74.072
I2C_3_DSI_SCL_JMP: J5.16 J5B.8 R76.2 U85.12 | length 265.9
  Top Layer w0.15: v1(210.204,138.981) 211.048,139.825 U85.12@213.121,139.825
  INT2_SIG w0.15: J5.16@57.81,21.08 59.073,19.817 59.073,19.693 59.07,19.69 59.07,18.183 59.763,17.49 70.71,17.49 72.2,16 80.041,16 88.341,24.3 112.025,24.3 113.225,23.1 115.481,23.1 126.581,34.2 156.145,34.2 162.145,40.2 164.215,40.2 167.515,43.5 176.785,43.5 184.084,50.799 184.084,54.584 187.2,57.7 202.97,57.7 203.6,58.33 203.6,115.417 212.33,124.148 212.33,134.619 210.204,136.746 v1(210.204,138.981)
  Bottom Layer w0.15: R76.2@49.955,21.08 J5B.8@52.73,21.08 J5.16@57.81,21.08
I2C_3_DSI_SDA_JMP: J5.14 J5B.7 R75.2 U85.13 | length 265
  Top Layer w0.15: v1(210.85,138.473) 211.552,139.175 U85.13@213.121,139.175
  INT2_SIG w0.15: J5.14@57.81,18.54 59.25,17.1 70.4,17.1 71.876,15.624 80.561,15.624 88.838,23.9 111.2,23.9 112.6,22.5 115.775,22.5 126.875,33.6 156.11,33.6 162.31,39.8 164.381,39.8 167.681,43.1 177.885,43.1 184.639,49.854 184.639,53.339 186.5,55.2 203.82,55.2 204.3,55.68 204.3,114.705 212.751,123.156 212.751,135.076 210.85,136.977 v1(210.85,138.473)
  Bottom Layer w0.15: R75.2@49.955,18.54 J5B.7@52.73,18.54 J5.14@57.81,18.54
I2C_4_CSI1_SCL: M1.A13 RA26.1 | length 36
  Top Layer w0.15: M1.A13@148.813,84.9 148.813,86.731 147.525,88.018 147.525,91.89 148.31,92.675 150.852,92.675 152.727,90.8 154.295,90.8 158.061,87.035 158.061,82.592 163.785,76.867 RA26.1@163.785,74.128
I2C_4_CSI1_SCL_JMP: J6.12 J6B.6 R410.1 U81.3 | length 60.6
  Top Layer w0.15: U81.3@225.12,104.665 226.229,104.665 v1(227.409,103.485)
  Bottom Layer w0.15: J6.12@197.09,64.1 J6B.6@201.665,64.1 ; J6B.6@202.17,64.1 230.6,92.53 230.6,100.294 v1(227.409,103.485) R410.1@227.409,104.225
I2C_4_CSI1_SDA: M1.A12 RA26.2 | length 35
  Top Layer w0.15: M1.A12@149.448,84.9 149.448,86.741 147.902,88.286 147.902,91.843 148.434,92.375 150.643,92.375 152.576,90.441 154.152,90.441 157.724,86.87 157.724,82.453 163.286,76.891 RA26.2@163.286,74.128
I2C_4_CSI1_SDA_JMP: J6.10 J6B.5 R409.1 U81.4 | length 58
  Top Layer w0.15: U81.4@225.12,104.015 225.122,104.013 225.967,104.013 v1(226.495,103.485)
  Bottom Layer w0.15: J6.10@197.09,66.64 200.84,66.64 J6B.5@202.17,66.64 202.853,66.64 203.425,66.64 230.043,93.258 230.043,99.937 v1(226.495,103.485) 226.495,104.146 R409.1@226.416,104.225
I2C_5_CSI2_SCL: M1.C06 RA27.4 | length 9.8
  Top Layer w0.15: M1.C06@153.257,80.3 154.755,78.802 156.449,78.802 159.703,75.547 RA27.4@159.703,74.128
I2C_5_CSI2_SCL_JMP: J6.24 J6B.12 R412.1 U88.3 | length 63.8
  Top Layer w0.15: U88.3@225.404,82.74 226.514,82.74 v1(227.694,81.56)
  Bottom Layer w0.15: J6.24@197.09,48.86 202.105,48.86 210.291,57.046 225.868,57.046 231.1,62.277 231.1,77.7 227.765,81.035 227.765,81.489 v1(227.694,81.56) R412.1@227.694,82.3
I2C_5_CSI2_SDA: M1.C05 RA27.3 | length 9.7
  Top Layer w0.15: M1.C05@153.892,80.3 154.992,79.2 156.475,79.2 160.203,75.472 RA27.3@160.203,74.128
I2C_5_CSI2_SDA_JMP: J6.22 J6B.11 R411.1 U88.4 | length 60.1
  Top Layer w0.15: U88.4@225.404,82.09 225.407,82.088 226.252,82.088 v1(226.779,81.56)
  Bottom Layer w0.15: J6.22@197.09,51.4 J6B.11@202.17,51.4 208.704,57.934 224.179,57.934 230.7,64.455 230.7,77.639 v1(226.779,81.56) 226.779,82.221 R411.1@226.7,82.3
I2C_6_SCL: M1.C19 RA45.1 | length 20.3
  Top Layer w0.15: M1.C19@145.002,80.3 145.002,80.805 144.833,80.973 144.833,81.651 145.002,81.82 v1(145.002,81.941)
  INT2_SIG w0.15: v1(145.002,81.941) 145.002,81.856 144.255,81.109 144.255,72.167 146.417,70.005 v1(148.475,70.005)
  Bottom Layer w0.15: v1(148.475,70.005) 149.35,70.88 RA45.1@149.35,72.95
I2C_6_SCL_JMP: J11.8 J11B.4 R427.2 U11.3 | length 48.8
  Top Layer w0.15: J11.8@129.42,134.43 J11B.4@129.42,139.51 ; v1(137.909,149.4) 138.434,148.875 139.99,148.875 146.741,155.626 154.951,155.626 156.175,156.849 156.175,159.029 157.535,160.389 157.535,161.384 157.447,161.472 U11.3@156.603,161.472
  Bottom Layer w0.15: J11B.4@129.42,139.51 R427.2@129.42,141.725 133.594,141.725 137.961,146.092 137.961,149.348 v1(137.909,149.4)
I2C_6_SDA: M1.C18 RA45.2 | length 16.9
  Top Layer w0.15: v1(145.358,81.205) 145.358,81.083 145.637,80.805 M1.C18@145.637,80.3
  INT2_SIG w0.15: v1(145.358,81.205) 144.673,80.52 144.673,72.403 146.564,70.512 147.766,70.512 v1(147.783,70.53)
  Bottom Layer w0.15: v1(147.783,70.53) 147.801,70.53 148.85,71.579 RA45.2@148.85,72.95
I2C_6_SDA_JMP: J11.6 J11B.3 R426.2 U11.4 | length 50.9
  Top Layer w0.15: J11.6@126.88,134.43 J11B.3@126.88,139.51 ; v1(138.659,149.4) 139.945,149.4 141.556,151.01 141.556,151.925 145.556,155.926 154.515,155.926 155.875,157.286 155.875,159.379 156.6,160.104 U11.4@156.6,160.825
  Bottom Layer w0.15: R426.2@126.88,141.725 J11B.3@126.88,139.51 127.99,138.4 130.927,138.4 138.659,146.132 v1(138.659,149.4)
I2C_DDC_SCL: J44.52 R469.1 U85.10 | length 21
  Top Layer w0.15: J44.52@212.767,154.35 212.767,144.76 211.714,143.706 211.714,141.532 212.121,141.125 U85.10@213.121,141.125 214.482,141.125 215.75,139.857 R469.1@215.75,136.86
I2C_DDC_SDA: J44.54 R468.1 U85.9 | length 21.6
  Top Layer w0.15: U85.9@212.962,141.775 212.101,141.775 212.014,141.863 212.014,143.569 213.402,144.957 J44.54@213.402,154.35 ; U85.9@213.042,141.855 U85.9@213.121,141.775 214.753,141.775 216.8,139.728 R468.1@216.8,136.86
I2C_DSI_SCL: J44.6 R472.1 U85.6 | length 35.5
  Top Layer w0.15: J44.6@198.162,154.35 v1@198.162,155.742 ; v1(216.426,151.153) 216.5,151.079 216.5,150.311 216.5,143.075 217.8,141.775 U85.6@219.021,141.775 219.981,141.775 220.809,142.603 R472.1@221.484,142.603
  INT2_SIG w0.15: v1(198.161,155.744) 199.977,153.928 210.898,153.928 213.292,151.534 216.044,151.534 v1(216.426,151.153)
I2C_DSI_SDA: J44.4 R471.1 U85.5 | length 35.5
  Top Layer w0.15: v1(197.529,152.956) J44.4@197.527,154.35 ; v1(215.889,150.614) 215.934,150.57 215.934,142.853 217.661,141.125 U85.5@219.021,141.125 219.981,141.125 220.462,141.606 R471.1@221.484,141.606
  INT2_SIG w0.15: v1(197.529,152.956) 198.173,153.6 210.398,153.6 213.383,150.614 v1(215.889,150.614)
I2S_1_BCLK: M1.B20 RA18.1 | length 47.4
  Top Layer w0.15: v1(142.58,81.663) 143.33,81.663 M1.B20@144.367,82.7
  INT2_SIG w0.15: v1(132.383,104.067) 132.383,105.596 133.787,107 134.998,107 135.886,106.112 143.532,106.112 144.555,105.088 144.555,99.88 142.641,97.966 142.641,81.724 v1(142.58,81.663)
  Bottom Layer w0.15: v1(132.383,104.067) 132.4,104.05 134.435,104.05 136.431,106.045 RA18.1@136.431,107
I2S_1_BCLK_JMP: J3.1 J3B.1 U52.29 | length 93.3
  Top Layer w0.15: J3.1@164.9,134.43 J3B.1@164.9,139.51 ; v1(236.2,173.925) 236.322,173.925 236.472,174.075 U52.29@237.546,174.075
  Bottom Layer w0.15: J3B.1@164.9,139.51 168.147,142.757 172.157,142.757 196.6,167.2 231.583,167.2 236.2,171.817 v1(236.2,173.925)
I2S_1_D_IN: M1.B23 RA18.4 | length 35.3
  Top Layer w0.15: v1(140.996,84.127) 141.021,84.127 141.938,83.21 142.23,83.21 142.462,82.978 M1.B23@142.462,82.7
  INT2_SIG w0.15: v1(134.298,105.61) 134.948,104.96 143.04,104.96 143.4,104.6 143.4,101.4 140.448,98.448 140.448,84.675 v1(140.996,84.127)
  Bottom Layer w0.15: v1(134.298,105.61) 134.931,106.242 RA18.4@134.931,107
I2S_1_D_IN_JMP: J3.7 J3B.4 U52.31 | length 101.5
  Top Layer w0.15: J3.7@157.28,134.43 J3B.4@157.28,139.51 ; v1(234.05,173.95) 234.67,173.95 234.925,173.694 234.925,173.691 235.233,173.384 235.284,173.384 235.567,173.1 236.542,173.1 236.717,173.275 U52.31@237.546,173.275
  Bottom Layer w0.15: J3B.4@157.28,139.51 164.07,146.3 174.003,146.3 196.103,168.4 230.956,168.4 233.997,171.44 233.997,173.897 v1(234.05,173.95)
I2S_1_D_OUT: M1.B22 RA18.3 | length 39
  Top Layer w0.15: v1(141.815,84.097) 142.792,83.12 142.792,83.029 143.097,82.724 M1.B22@143.097,82.7
  INT2_SIG w0.15: v1(133.627,105.276) 133.646,105.295 133.646,105.841 134.005,106.2 134.624,106.2 135.468,105.356 143.181,105.356 143.78,104.757 143.78,101.313 140.778,98.311 140.778,85.134 v1(141.815,84.097)
  Bottom Layer w0.15: v1(133.627,105.276) 133.741,105.276 133.947,105.07 134.522,105.07 134.838,105.386 135.431,105.979 RA18.3@135.431,107
I2S_1_D_OUT_JMP: J3.5 J3B.3 U52.32 | length 98.4
  Top Layer w0.15: J3.5@159.82,134.43 J3B.3@159.82,139.51 ; v1(234.522,173.356) 234.643,173.356 234.949,173.05 235.193,173.05 235.443,172.8 236.666,172.8 236.741,172.875 U52.32@237.546,172.875
  Bottom Layer w0.15: J3B.3@159.69,139.38 166.21,145.9 174.169,145.9 196.269,168 231.139,168 234.522,171.383 v1(234.522,173.356)
I2S_1_MCLK: M1.B24 RA19.1 | length 59.4
  Top Layer w0.15: v1(140.35,81.882) 141.009,81.882 M1.B24@141.827,82.7
  INT2_SIG w0.15: v1(136.91,93.246) 136.91,83.011 137.601,82.32 139.912,82.32 v1(140.35,81.882)
  Bottom Layer w0.15: RA19.1@106.55,88.25 106.558,88.242 106.558,87.739 108.5,85.797 108.5,85.108 109.15,84.458 109.15,81.188 110.015,80.323 114.261,80.323 115.494,81.556 116.609,81.556 117.226,80.94 118.158,80.94 121.404,84.186 123.068,84.186 123.871,84.989 123.871,87.239 129.878,93.246 v1(136.91,93.246)
I2S_1_MCLK_JMP: J3.9 J3B.5 U52.28 | length 104
  Top Layer w0.15: J3.9@154.74,134.43 J3B.5@154.74,139.51 ; v1(233.303,173.55) 233.386,173.633 233.386,174.029 233.833,174.475 U52.28@237.546,174.475
  Bottom Layer w0.15: J3B.5@154.74,139.51 161.93,146.7 173.837,146.7 195.937,168.8 230.88,168.8 233.303,171.223 v1(233.303,173.55)
I2S_1_SYNC: M1.B21 RA18.2 | length 43.9
  Top Layer w0.15: v1(141.913,82.006) 142.035,82.006 142.262,82.234 143.266,82.234 M1.B21@143.732,82.7
  INT2_SIG w0.15: v1(132.95,104.6) 132.95,105.645 133.904,106.6 134.775,106.6 135.629,105.746 143.38,105.746 144.189,104.937 144.189,100.157 142.34,98.307 142.34,83.065 141.925,82.65 141.925,82.019 v1(141.913,82.006)
  Bottom Layer w0.15: v1(132.95,104.6) 134.519,104.6 135.931,106.012 RA18.2@135.931,107
I2S_1_SYNC_JMP: J3.3 J3B.2 U52.30 | length 96.4
  Top Layer w0.15: J3.3@162.36,134.43 J3B.2@162.36,139.51 ; v1(235.45,173.909) 235.959,173.4 236.417,173.4 236.692,173.675 U52.30@237.546,173.675
  Bottom Layer w0.15: J3B.2@162.174,139.324 168.35,145.5 174.334,145.5 196.434,167.6 231.32,167.6 235.45,171.73 v1(235.45,173.909)
I2S_2_BCLK: M1.B26 RA22.4 | length 26.3
  Top Layer w0.15: v1(140.189,84.113) 140.189,84.075 140.557,83.707 M1.B26@140.557,82.7
  INT2_SIG w0.15: v1(140.189,84.113) 139.2,85.101 139.2,101.441 v1(140.517,102.759)
  Bottom Layer w0.15: v1(140.517,102.759) 140.517,104.33 142.65,106.463 RA22.4@142.65,107
I2S_2_BCLK_DSI: J12.2 J12B.1 J44.42 JP3.1 | length 132.3
  Top Layer w0.15: J44.42@209.592,154.35 209.592,153.15 v1(209.592,149.612) 209.592,148.383 JP3.1@209.625,148.35
  INT2_SIG w0.15: J12B.1@202.17,43.86 205.487,43.86 208.4,46.773 208.4,78 215.8,85.4 215.8,110.8 216.067,111.067 216.067,112.742 216.575,113.25 216.575,114.925 216.225,115.275 216.225,118.097 217.578,119.45 217.578,127.447 219.3,129.169 219.3,143.547 214.147,148.7 210.505,148.7 v1(209.592,149.612)
  Bottom Layer w0.15: J12.2@197.09,43.86 J12B.1@202.17,43.86
I2S_2_BCLK_M2B: J12.10 J12B.5 J39.20 | length 63.2
  Top Layer w0.15: J39.20@145.55,19.775 145.55,19.835 145.565,19.85 145.565,20.062 145.885,20.382 146.332,20.382 v1(146.41,20.46)
  Bottom Layer w0.15: v1(146.41,20.46) 147.43,21.48 151.377,21.48 151.683,21.175 152.117,21.175 152.423,21.48 154.947,21.48 158.142,24.675 170.188,24.675 170.653,24.21 178.006,24.21 186.285,32.488 195.878,32.488 J12.10@197.09,33.7 J12B.5@202.17,33.7
I2S_2_D_IN: M1.B29 RA22.1 | length 29.6
  Top Layer w0.15: v1(138.011,84.097) 138.652,83.456 M1.B29@138.652,82.7
  INT2_SIG w0.15: v1(138.011,84.097) 137.25,84.858 137.25,85.85 138.16,86.76 138.16,102.708 139.94,104.487 141.85,104.487 142.027,104.31 142.606,104.31 v1(142.61,104.306)
  Bottom Layer w0.15: v1(142.61,104.306) 142.61,104.314 144.15,105.854 RA22.1@144.15,107
I2S_2_D_IN_DSI: J12.8 J12B.4 J44.48 | length 139
  Top Layer w0.15: J44.48@211.497,154.35 211.496,154.349 211.496,151.526 211.8,151.222 v1(211.8,151.213)
  INT2_SIG w0.15: J12B.4@202.17,36.24 206.64,36.24 210.9,40.5 210.9,78.9 217,85 217,110.1 217.8,110.9 217.8,116.02 217.475,116.345 217.475,117.535 218.9,118.96 218.9,126.728 220.8,128.628 220.8,144.556 215.089,150.268 212.746,150.268 v1(211.8,151.213)
  Bottom Layer w0.15: J12.8@197.09,36.24 J12B.4@202.17,36.24
I2S_2_D_IN_M2B: J12.16 J12B.8 J39.24 | length 59.7
  Top Layer w0.15: J39.24@145.55,18.775 146.72,18.775 v1(147.82,19.875)
  Bottom Layer w0.15: v1(147.82,19.875) 148.295,20.35 151.235,20.35 151.31,20.275 152.49,20.275 152.565,20.35 155.337,20.35 156.612,21.625 185.12,21.625 188.295,24.8 195.81,24.8 J12.16@197.09,26.08 J12B.8@202.17,26.08
I2S_2_D_OUT: M1.B28 RA22.2 | length 27.6
  Top Layer w0.15: M1.B28@139.287,82.7 v1(139.287,83.225)
  INT2_SIG w0.15: v1(139.287,83.225) 138.6,83.912 138.6,102.451 140.094,103.945 v1(141.65,103.945)
  Bottom Layer w0.15: v1(141.65,103.945) 141.65,104.067 141.799,104.217 141.799,104.238 143.65,106.089 RA22.2@143.65,107
I2S_2_D_OUT_DSI: J12.6 J12B.3 J44.46 JP4.1 | length 138.2
  Top Layer w0.15: J44.46@210.862,154.35 210.862,151.512 210.987,151.387 v1(210.987,150.793) 210.987,148.634 JP4.1@210.928,148.575
  INT2_SIG w0.15: J12B.3@202.17,38.78 205.68,38.78 210.1,43.2 210.1,78.6 216.6,85.1 216.6,110.4 217.4,111.2 217.4,111.865 217.417,111.883 217.417,112.317 217.4,112.335 217.4,115.7 217.1,116 217.1,117.679 218.521,119.1 218.521,126.989 220.236,128.704 220.236,144.264 214.748,149.752 212.028,149.752 v1(210.987,150.793)
  Bottom Layer w0.15: J12.6@197.09,38.78 J12B.3@202.17,38.78
I2S_2_D_OUT_M2B: J12.14 J12B.7 J39.22 | length 60.6
  Top Layer w0.15: J39.22@145.55,19.275 145.572,19.297 146.462,19.297 v1@147.813,20.647
  Bottom Layer w0.15: v1(147.82,20.655) 147.826,20.65 148.711,20.65 148.811,20.75 151.259,20.75 151.434,20.575 152.366,20.575 152.541,20.75 155.225,20.75 156.4,21.925 182.99,21.925 188.435,27.37 195.84,27.37 J12.14@197.09,28.62 J12B.7@202.17,28.62
I2S_2_SYNC: M1.B27 RA22.3 | length 27
  Top Layer w0.15: v1(139.279,84.088) 139.922,83.445 M1.B27@139.922,82.7
  INT2_SIG w0.15: v1(139.279,84.088) 138.9,84.467 138.9,102.044 140.223,103.367 v1(141.098,103.367)
  Bottom Layer w0.15: v1(141.098,103.367) 141.098,104.237 143.15,106.289 RA22.3@143.15,107
I2S_2_SYNC_DSI: J12.4 J12B.2 J44.44 | length 133.2
  Top Layer w0.15: v1(210.227,150.268) J44.44@210.227,154.35
  INT2_SIG w0.15: J12B.2@202.17,41.32 205.316,41.32 209.3,45.305 209.3,78.3 216.2,85.2 216.2,110.6 216.367,110.767 216.367,112.618 216.875,113.126 216.875,115.465 216.707,115.632 216.707,117.95 218.075,119.317 218.075,127.21 219.755,128.89 219.755,143.945 214.469,149.231 211.264,149.231 v1(210.227,150.268)
  Bottom Layer w0.15: J12.4@197.09,41.32 J12B.2@202.17,41.32
I2S_2_SYNC_M2B: J12.12 J12B.6 J39.28 | length 65.2
  Top Layer w0.15: J39.28@145.551,17.774 v1@147.159,17.774
  Bottom Layer w0.15: v1(147.16,17.773) 147.16,20.737 147.603,21.18 151.253,21.18 151.558,20.875 152.242,20.875 152.547,21.18 155.12,21.18 158.315,24.375 169.055,24.375 170.355,23.075 178.265,23.075 185.138,29.948 195.878,29.948 J12.12@197.09,31.16 J12B.6@202.17,31.16
ILIM_VBUS: R395.1 R404.2 U22.6 | length 21.5
  Top Layer w0.15: v1(137.041,175.911) 137.041,177.826 R404.2@137.03,177.838 137.805,178.613 137.855,178.613 R395.1@138.08,178.838 ; v1(152.987,173.536) 152.996,173.545 U22.6@152.996,174.465
  Bottom Layer w0.15: v1(137.041,175.911) 137.05,175.911 137.354,176.215 149.343,176.215 152.023,173.536 v1(152.987,173.536)
IN2L: C337.2 R215.1 U52.26 | length 21.9
  Top Layer w0.15: R215.1@231.45,160.5 232.35,160.5 v1(232.35,159.721) ; v1(232.563,173.668) 232.602,173.668 233.858,174.925 235.168,174.925 235.518,175.275 235.733,175.275 235.983,175.525 236.417,175.525 236.667,175.275 U52.26@237.546,175.275
  INT2_SIG w0.15: v1(232.35,159.721) 232.35,162.209 231.925,162.634 231.925,165 232.563,165.638 v1(232.563,173.668)
IN2L_A: C337.1 C340.2 R421.2 R422.1 | length 3.8
  Top Layer w0.15: C337.1@232.35,161.5 C340.2@233.7,161.5 R422.1@233.7,162.9 R421.2@232.6,162.9
IN2L_CONN: J69.2 R422.2 | length 8.1
  Top Layer w0.15: R422.2@233.7,163.9 234.425,163.175 234.425,157.115 J69.2@233.71,156.4
IN2R: C335.2 R419.1 U52.24 | length 19.6
  Top Layer w0.15: v1(237.121,176.2) U52.24@238.071,176.2 ; v1(237.6,159.721) 237.6,160.5 R419.1@238.5,160.5
  INT2_SIG w0.15: v1(237.121,176.2) 237.121,172.391 236.725,171.995 236.725,163.75 237.6,162.875 v1(237.6,159.721)
IN2R_A: C335.1 C339.2 R420.2 R423.1 | length 3.9
  Top Layer w0.15: R420.2@237.35,162.9 R423.1@236.25,162.9 C339.2@236.25,161.5 C335.1@237.6,161.5
IN2R_CONN: J69.3 R423.2 | length 8.1
  Top Layer w0.15: J69.3@236.25,156.4 235.488,157.162 235.488,163.138 R423.2@236.25,163.9
JMP_JTAG: J58.2 R283.2 U59.1 | length 20.3
  Top Layer w0.15: J58.2@78.55,51.388 80.888,51.388 83.9,54.4 90.514,54.4 91.614,53.3 R283.2@95.015,53.3 95.9,53.3 U59.1@97.187,53.3
JTAG1_TRST#: M1.C07 Q31.3 R463.1 | length 100.4
  Top Layer w0.15: Q31.3@76.7,55.475 78,55.475 78.15,55.325 80.175,55.325 80.4,55.1 R463.1@81.05,54.45 ; R463.1@81.05,54.4 R463.1@81.05,54.45 ; v1(83.2,55.1) 82.55,54.45 R463.1@81.05,54.45 ; M1.C07@152.622,80.3 152.658,80.336 152.658,80.733 153.067,81.142 153.661,81.142 v1(153.747,81.228)
  INT2_SIG w0.15: v1(83.2,55.1) 88.311,55.1 90.211,57 99.1,57 99.5,56.6 106.177,56.6 112.494,62.917 143.604,62.917 147.172,66.485 151.585,66.485 152.636,67.536 153.466,67.536 155.942,70.012 155.942,77.403 155.337,78.008 155.337,79.67 155.249,79.758 155.217,79.758 v1(153.747,81.228)
JTAG_1_TCK: J57.2 M1.C11 U59.7 | length 120.8
  Top Layer w0.15: J57.2@90.8,29.62 95.16,33.98 95.16,49.567 95.35,49.756 95.893,50.3 U59.7@97.187,50.3 98.014,50.3 99.714,48.6 103.2,48.6 128.107,48.6 135.4,55.893 v1(135.4,55.946) ; M1.C11@150.082,80.3 150.082,79.828 150.985,78.925 151.905,78.925 152.204,79.224 v1(152.326,79.224)
  INT2_SIG w0.15: v1(135.4,55.946) 135.471,55.875 140.753,55.875 142.032,57.154 149.275,57.154 155.482,63.36 155.482,65.386 159.359,69.263 159.359,76.108 156.887,78.579 156.887,81.087 155.375,82.6 153.31,82.6 152.326,81.616 v1(152.326,79.224)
